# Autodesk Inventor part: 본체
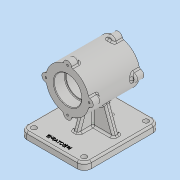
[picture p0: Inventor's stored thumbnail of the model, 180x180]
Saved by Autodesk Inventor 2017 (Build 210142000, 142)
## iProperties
Part Number: 본체
Material: 일반
Document SubType Name: Modeling
Designer: MRC
Density: 1 g/cm^3
Appearance: 기본값
Mass: 452.843 g
Surface Area: 800.379 cm^2
Volume: 452.843 cm^3
Author: MRC
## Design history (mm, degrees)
sketch "스케치1"
  geometry: L1 (-43.5, 0)-(43.5, 0); L2 (-43.5, 23.5)-(-24.5, 23.5); L3 (-24.5, 23.5)-(-24.5, 21); L4 (-24.5, 21)-(24.5, 21); L5 (24.5, 21)-(24.5, 23.5); L6 (24.5, 23.5)-(43.5, 23.5); L7 (43.5, 23.5)-(43.5, 37); L8 (43.5, 37)-(-43.5, 37); L9 (-43.5, 37)-(-43.5, 23.5); 2 further points
  constraints: 18 end point, 5 perpendicular, 4 point on line, 2 horizontal, 1 coincident, 1 midpoint, 1 vertical
  dimensions: "d0" = 87 distance of L1.start L1.end; "d1" = 42 diameter of L4 L1; "d2" = 47 diameter of L6 L1; "d3" = 74 diameter of L8 L1; "d4" = 19 distance between parallel lines of L3 L9; "d5" = 19 distance between parallel lines of L7 L5
revolve "회전1" sketch "스케치1" stored, may be unused: angle "d6" = 90 deg
fillet "모깎기1" dims "d7" = 1
chamfer "모따기1" distance "d8" = 1; stored, may be unused: second distance "d9" = 2, angle "d10" = 45 deg
chamfer "모따기2" distance "d11" = 1; stored, may be unused: second distance "d12" = 2, angle "d13" = 45 deg
sketch "스케치2"
  geometry: A1 r 7 centre (0, 37) between (6.969, 36.338) and (-6.969, 36.338); A2 r 37 centre (0, 0) between (0, 37) and (-6.969, 36.338) reference; 1 further point
  constraints: 5 point on circle, 1 centre point, 1 vertical alignment
  dimensions: "d14" = 14 diameter of A1
extrude "돌출1" join sketch "스케치2" distance "d15" = 14; taper "d16" = 0 deg
hole "구멍1" diameter "d19" = 3.242; stored, may be unused: countersink angle "d23" = 90 deg, drill point angle "d25" = 118 deg; dims "d17" = 10, "d18" = 10, "d20" = 8, "d21" = 4, "d22" = 2, "d24" = 10
fillet "모깎기2" dims "d29" = 3
fillet "모깎기3" dims "d30" = 3
sketch "스케치3"
  geometry: L1 (-70, -70)-(60, -70); L2 (60, -70)-(60, -82); L3 (60, -82)-(-70, -82); L4 (-70, -82)-(-70, -70); 1 further point
  constraints: 8 end point, 2 parallel, 1 horizontal, 1 perpendicular
  dimensions: "d31" = 12 distance of L1.end L2.end; "d32" = 130 distance of L2.end L3.end; "d33" = 82 distance from line of point (0, 0) L3; "d64" = 70 distance from line of point (0, 0) L4
extrude "돌출2" join sketch "스케치3" stored distance "d34" = 110; taper "d35" = 0 deg
fillet "모깎기4" dims "d36" = 12
sketch "스케치4"
  geometry: C1 r 4.5 at (0, 98); C2 r 4.5 at (106, 98); C3 r 4.5 at (106, 12); C4 r 4.5 at (0, 12); A1 r 12 centre (106, 98) between (118, 98) and (106, 110) reference; A2 r 12 centre (0, 98) between (0, 110) and (-12, 98) reference; A3 r 12 centre (0, 12) between (-12, 12) and (0, 0) reference; A4 r 12 centre (106, 12) between (106, 0) and (118, 12) reference; 1 further point
  constraints: 4 centre point, 4 concentric, 3 equal radius
  dimensions: "d37" = 9 diameter of C1
extrude "돌출3" cut sketch "스케치4" stored distance "d38" = 110; taper "d39" = 0 deg
fillet "모깎기5" dims "d40" = 3
sketch "스케치5"
  geometry: L1 (53, 57)-(63, 57); L2 (63, 57)-(63, 47); L3 (63, 47)-(53, 47); L4 (53, 47)-(53, 57); 3 further points
  constraints: 8 end point, 2 midpoint, 2 parallel, 1 horizontal, 1 horizontal alignment, 1 perpendicular, 1 vertical alignment
  dimensions: "d41" = 10 distance of L1.start L1.end; "d42" = 10 distance of L1.end L2.end
extrude "돌출4" join sketch "스케치5" stored distance "d43" = 110; taper "d44" = 0 deg
sketch "스케치6"
  geometry: L1 (30, -70)-(19.725, -41.769); L2 (-58, -70)-(48, -70) reference; 1 further point
  constraints: 2 end point, 1 point on line
  dimensions: "d45" = 110 deg angle of L2 L1; "d46" = 30 horizontal distance of L1.start point (0, 0)
feature "리브1" sketch "스케치6" dims "d47" = 1, "d48" = 10, "d49" = 0, "d50" = 0, "d51" = 1, "d52" = 1
sketch "스케치7"
  geometry: L1 (-44.465, -31.706)-(-70, -41); L2 (-70, 43)-(-70, -43) reference; L3 (-73, -55)-(-82, -55) reference; 1 further point
  constraints: 2 end point, 1 point on line
  dimensions: "d53" = 110 deg angle of L2 L1; "d54" = 14 distance from line of L3 L1.end
feature "리브2" sketch "스케치7" dims "d55" = 1, "d56" = 10, "d57" = 0, "d58" = 0, "d59" = 1, "d60" = 1
fillet "모깎기6" dims "d61" = 3
fillet "모깎기7" dims "d62" = 3
sketch "스케치8"
  geometry: 2 further points
  constraints: 1 horizontal alignment, 1 other
  dimensions: "d63" = 58 distance of point (58, -52) point (0, -52)
feature "엠보싱1" sketch "스케치8" dims "d0" = 87, "d1" = 42, "d2" = 47, "d3" = 74, "d4" = 19, "d5" = 19, "d65" = 0.5, "d66" = 0
sketch "스케치9"
  geometry: 1 further point
node "솔리드1"
pattern_circular "원형 패턴1" dims angle "d27" = 360 deg
mirror "미러1"
mirror "미러2"
mirror "미러3"
